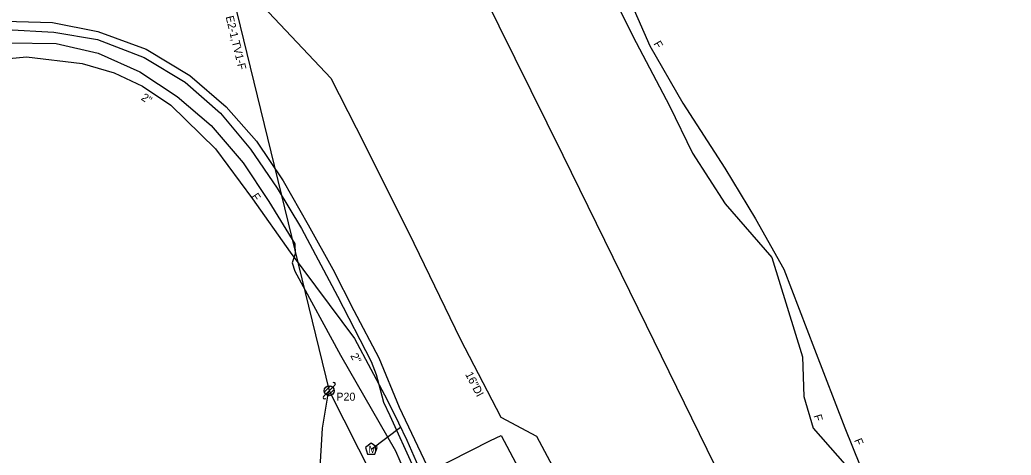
# Model space of a CAD drawing. Extents: x 1741604 to 1825760, y 1164229 to 1194908.
# Drawn here: x 1755344.5 to 1755839.8, y 1168745.3 to 1168962.9 of the extents above; entities that cross this region are included whole.
import ezdxf

# ---------------------------------------------------------------- set-up
doc = ezdxf.new("R2010")
doc.units = 0
for name, color, linetype in [('RD_EX_SU_Elec', 7, 'Continuous'), ('RD_EX_SU_H2O', 7, 'Continuous'), ('RD_EX_SU_Ovhd', 7, 'Continuous'), ('RD_EX_SU_Pole', 7, 'Continuous'), ('RD_EX_SU_Sewer', 7, 'Continuous'), ('RD_EX_SU_Telecom', 7, 'Continuous'), ('RD_EX_SU_TX_H2O', 7, 'Continuous'), ('RD_EX_SU_TX_Pole', 7, 'Continuous'), ('RD_EX_SU_TX_Telecom', 7, 'Continuous')]:
    doc.layers.add(name, color=color, linetype=linetype)

msp = doc.modelspace()

# ---------------------------------------------------------------- linework, layer by layer
at = {"layer": 'RD_EX_SU_Elec'}
msp.add_lwpolyline([(1755352.15, 1168636.03), (1755355.71, 1168639.76), (1755360.62, 1168642.49), (1755377.96, 1168648.25), (1755395.32, 1168654.04), (1755407.08, 1168658.47), (1755416.27, 1168664.85), (1755426.19, 1168674.91), (1755444.85, 1168693.91), (1755458.49, 1168705.44), (1755480.84, 1168720.11), (1755488.48, 1168726.7), (1755492.01, 1168730.8), (1755494.34, 1168736.34), (1755495.74, 1168758.73), (1755498.75, 1168776.84)], dxfattribs=at)
at = {"layer": 'RD_EX_SU_H2O'}
msp.add_line((1755520.4, 1168748.47), (1755534.69, 1168759.32), dxfattribs=at)
for points in [[(1755385.42, 1169098.44), (1755401.32, 1169066.46), (1755415.89, 1169036.4), (1755422.95, 1169020.76), (1755426.26, 1169009.34), (1755463.14, 1168972.48), (1755499.82, 1168933.69), (1755512.6, 1168909), (1755538.91, 1168856.4), (1755564.45, 1168803.54), (1755584.77, 1168764.26), (1755602.59, 1168754.78), (1755634.52, 1168695.09), (1755648.65, 1168669.94), (1755682.22, 1168606.15), (1755709.26, 1168554.06), (1755726.87, 1168521.3)], [(1755317.93, 1168941.55), (1755347.73, 1168944.49), (1755375.7, 1168941.09), (1755391.63, 1168936.36), (1755405.8, 1168929.69), (1755420, 1168920.26), (1755442.22, 1168898.37), (1755460.76, 1168873.49), (1755479.47, 1168846.77), (1755511.72, 1168803.69), (1755527.96, 1168773), (1755533.67, 1168761.43), (1755537.79, 1168752.87), (1755543.72, 1168739.55)]]:
    msp.add_lwpolyline(points, dxfattribs=at)
msp.add_lwpolyline([(1755520.04, 1168751.27), (1755517.14, 1168749.16), (1755518.25, 1168745.75), (1755521.84, 1168745.75), (1755522.94, 1168749.16)], close=True, dxfattribs=at)
at = {"layer": 'RD_EX_SU_Ovhd'}
for p, q in [((1755435.58, 1169037.63), (1755499.08, 1168777.54)), ((1755499.08, 1168777.54), (1755611.8, 1168554.19))]:
    msp.add_line(p, q, dxfattribs=at)
at = {"layer": 'RD_EX_SU_Pole'}
for p, q in [((1755496.66, 1168776.89), (1755499.72, 1168779.95)), ((1755497.31, 1168775.77), (1755500.84, 1168779.31)), ((1755498.43, 1168775.13), (1755501.49, 1168778.19)), ((1755500.84, 1168779.31), (1755501.9, 1168780.37)), ((1755496.25, 1168774.71), (1755497.31, 1168775.77))]:
    msp.add_line(p, q, dxfattribs=at)
msp.add_circle((1755499.08, 1168777.54), 2.5, dxfattribs=at)
for centre, start, end in [((1755501.37, 1168780.9), 315, 135), ((1755496.78, 1168774.18), 135, 315)]:
    msp.add_arc(centre, 0.75, start, end, dxfattribs=at)
at = {"layer": 'RD_EX_SU_Sewer'}
msp.add_lwpolyline([(1755549.18, 1168737.18), (1755579.59, 1168752.57), (1755584.91, 1168755.1), (1755603.82, 1168719.72)], dxfattribs=at)
at = {"layer": 'RD_EX_SU_Telecom'}
for points in [[(1755590.16, 1169126.29), (1755590.98, 1169107.71), (1755588.59, 1169093.98), (1755585.74, 1169086.47), (1755598.29, 1169061.2), (1755650.69, 1168954.78), (1755669.04, 1168919.98), (1755680.52, 1168896.3), (1755696.94, 1168870.9), (1755720.15, 1168844.14), (1755735.51, 1168794.5), (1755736.19, 1168774.57), (1755740.79, 1168758.88), (1755761.5, 1168735.33), (1755775.66, 1168711.24), (1755791.36, 1168667.81), (1755799.39, 1168654.61), (1755819.15, 1168584.91), (1755822.92, 1168576.29), (1755830.76, 1168551.82), (1755839.8, 1168530.61)], [(1755643.16, 1168988.99), (1755650.24, 1168970.42), (1755659.27, 1168949.97), (1755675.7, 1168921.3), (1755696.74, 1168888.73), (1755711.98, 1168863.4), (1755726.14, 1168838.3), (1755741.49, 1168798.28), (1755756.63, 1168758.91), (1755772.29, 1168720.09), (1755790.19, 1168679.27), (1755805.71, 1168638.46), (1755819.76, 1168587.82), (1755820.42, 1168581.52)], [(1755575.8, 1168976.27), (1755615.82, 1168895.28), (1755657.46, 1168810.23), (1755699.13, 1168725.09)], [(1755336.84, 1168962.31), (1755360.73, 1168961.58), (1755383.48, 1168957.08), (1755407.65, 1168948.23), (1755429.34, 1168935), (1755447.51, 1168919.47), (1755462.71, 1168902.2), (1755476.06, 1168882.48), (1755488.57, 1168860.52), (1755500.87, 1168838.21), (1755511.35, 1168817.55), (1755523.89, 1168793.88), (1755533.94, 1168769.38), (1755547.81, 1168740.19)], [(1755337.65, 1168958.12), (1755361.46, 1168956.8), (1755383.25, 1168953.03), (1755406.57, 1168944.08), (1755427.09, 1168931.76), (1755444.74, 1168916.29), (1755459.8, 1168898.32), (1755473.09, 1168878.8), (1755485.28, 1168858.56), (1755503.24, 1168824.79), (1755520.07, 1168792.15), (1755522.53, 1168785.59), (1755524.49, 1168778.11), (1755526.21, 1168771.73), (1755529.29, 1168765.17), (1755541.09, 1168739.22)], [(1755338.86, 1168951.41), (1755362.56, 1168951.04), (1755383.58, 1168946.19), (1755404.43, 1168936.99), (1755423.08, 1168924.59), (1755439.99, 1168910.02), (1755455.99, 1168891.45), (1755468.93, 1168872.09), (1755481.86, 1168850.91), (1755482.08, 1168845.94), (1755480.47, 1168841.41), (1755481.82, 1168837.2), (1755504.75, 1168795.3), (1755532.15, 1168747.5), (1755536.58, 1168737.5)]]:
    msp.add_lwpolyline(points, dxfattribs=at)

# ---------------------------------------------------------------- texts
at = {"layer": 'RD_EX_SU_H2O'}
msp.add_text('M', height=3.75, dxfattribs=at).set_placement((1755518.61, 1168746.35))
at = {"layer": 'RD_EX_SU_Ovhd'}
msp.add_text('E2-1,TV1-F', height=4, rotation=283.7195, dxfattribs=at).set_placement((1755447.28, 1168964.42))
at = {"layer": 'RD_EX_SU_TX_H2O'}
for s, rotation, p in [('2"', 326.3944, (1755404.74, 1168923.2)), ('2"', 297.8865, (1755509.51, 1168795.04)), ('16"DI', 297.3571, (1755566.89, 1168785.77))]:
    msp.add_text(s, height=4, rotation=rotation, dxfattribs=at).set_placement(p)
at = {"layer": 'RD_EX_SU_TX_Pole'}
msp.add_text('P20', height=4, dxfattribs=at).set_placement((1755502.6, 1168772.54))
at = {"layer": 'RD_EX_SU_TX_Telecom'}
for rotation, p in [(299.8264, (1755660.97, 1168951.01)), (303.7459, (1755459.98, 1168874.68)), (286.354, (1755741.06, 1168765.06)), (291.963, (1755761.26, 1168752.78))]:
    msp.add_text('F', height=4, rotation=rotation, dxfattribs=at).set_placement(p)

doc.saveas('drawing.dxf')
